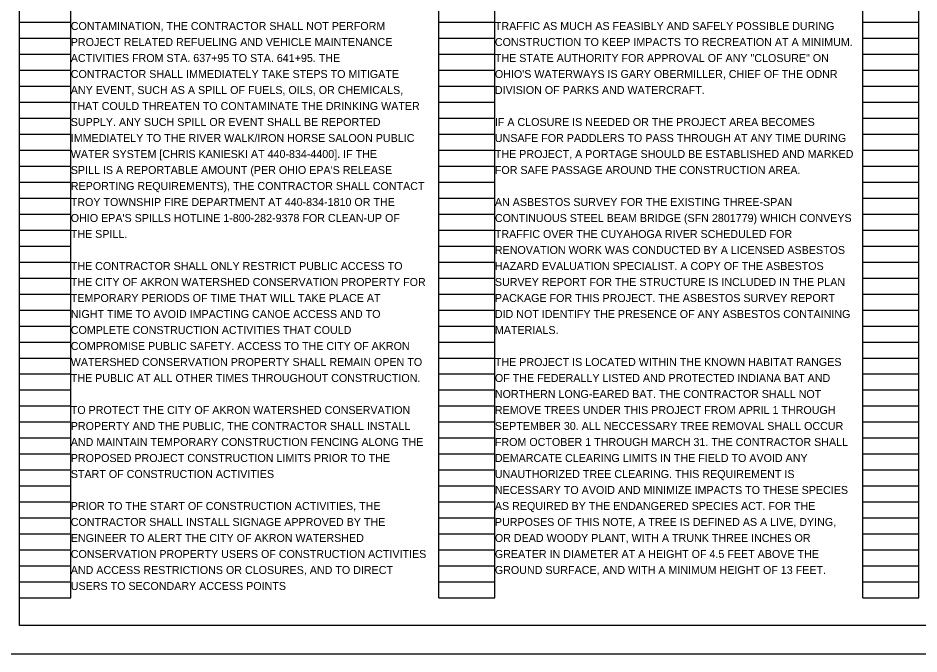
# Model space of a CAD drawing. Extents: x -6.4 to 41.8, y 0 to 22.
# Drawn here: x 1.98 to 17.74, y 0 to 11.13 of the extents above; entities that cross this region are included whole.
import ezdxf

# ---------------------------------------------------------------- set-up
doc = ezdxf.new("R2010")
doc.units = 0
for name, color, linetype in [('SC_Scratch1', 7, 'Continuous'), ('SH_Border', 7, 'Continuous'), ('SH_Cut_Line', 7, 'Continuous'), ('SH_Text', 7, 'Continuous')]:
    doc.layers.add(name, color=color, linetype=linetype)

msp = doc.modelspace()

# ---------------------------------------------------------------- linework, layer by layer
at = {"layer": 'SC_Scratch1'}
for p, q in [((2, 0.98), (2, 21.14)), ((2.9, 0.98), (2.9, 21.14)), ((9.34, 0.98), (9.34, 21.14)), ((10.32, 0.98), (10.32, 21.14)), ((16.76, 0.98), (16.76, 21.14)), ((17.74, 0.98), (17.74, 21.14)), ((2, 11.06), (2.9, 11.06)), ((9.34, 11.06), (10.32, 11.06)), ((16.76, 11.06), (17.74, 11.06)), ((2, 10.78), (2.9, 10.78)), ((9.34, 10.78), (10.32, 10.78)), ((16.76, 10.78), (17.74, 10.78)), ((2, 10.5), (2.9, 10.5)), ((9.34, 10.5), (10.32, 10.5)), ((16.76, 10.5), (17.74, 10.5)), ((2, 10.22), (2.9, 10.22)), ((9.34, 10.22), (10.32, 10.22)), ((16.76, 10.22), (17.74, 10.22)), ((2, 9.94), (2.9, 9.94)), ((9.34, 9.94), (10.32, 9.94)), ((16.76, 9.94), (17.74, 9.94)), ((2, 9.66), (2.9, 9.66)), ((9.34, 9.66), (10.32, 9.66)), ((16.76, 9.66), (17.74, 9.66)), ((2, 9.38), (2.9, 9.38)), ((9.34, 9.38), (10.32, 9.38)), ((16.76, 9.38), (17.74, 9.38)), ((2, 9.1), (2.9, 9.1)), ((9.34, 9.1), (10.32, 9.1)), ((16.76, 9.1), (17.74, 9.1)), ((2, 8.82), (2.9, 8.82)), ((9.34, 8.82), (10.32, 8.82)), ((16.76, 8.82), (17.74, 8.82)), ((2, 8.54), (2.9, 8.54)), ((9.34, 8.54), (10.32, 8.54)), ((16.76, 8.54), (17.74, 8.54)), ((2, 8.26), (2.9, 8.26)), ((9.34, 8.26), (10.32, 8.26)), ((16.76, 8.26), (17.74, 8.26)), ((2, 7.98), (2.9, 7.98)), ((9.34, 7.98), (10.32, 7.98)), ((16.76, 7.98), (17.74, 7.98)), ((2, 7.7), (2.9, 7.7)), ((9.34, 7.7), (10.32, 7.7)), ((16.76, 7.7), (17.74, 7.7)), ((2, 7.42), (2.9, 7.42)), ((9.34, 7.42), (10.32, 7.42)), ((16.76, 7.42), (17.74, 7.42)), ((2, 7.14), (2.9, 7.14)), ((9.34, 7.14), (10.32, 7.14)), ((16.76, 7.14), (17.74, 7.14)), ((2, 6.86), (2.9, 6.86)), ((9.34, 6.86), (10.32, 6.86)), ((16.76, 6.86), (17.74, 6.86)), ((2, 6.58), (2.9, 6.58)), ((9.34, 6.58), (10.32, 6.58)), ((16.76, 6.58), (17.74, 6.58)), ((2, 6.3), (2.9, 6.3)), ((9.34, 6.3), (10.32, 6.3)), ((16.76, 6.3), (17.74, 6.3)), ((2, 6.02), (2.9, 6.02)), ((9.34, 6.02), (10.32, 6.02)), ((16.76, 6.02), (17.74, 6.02)), ((2, 5.74), (2.9, 5.74)), ((9.34, 5.74), (10.32, 5.74)), ((16.76, 5.74), (17.74, 5.74)), ((2, 5.46), (2.9, 5.46)), ((9.34, 5.46), (10.32, 5.46)), ((16.76, 5.46), (17.74, 5.46)), ((2, 5.18), (2.9, 5.18)), ((9.34, 5.18), (10.32, 5.18)), ((16.76, 5.18), (17.74, 5.18)), ((2, 4.9), (2.9, 4.9)), ((9.34, 4.9), (10.32, 4.9)), ((16.76, 4.9), (17.74, 4.9)), ((2, 4.62), (2.9, 4.62)), ((9.34, 4.62), (10.32, 4.62)), ((16.76, 4.62), (17.74, 4.62)), ((2, 4.34), (2.9, 4.34)), ((9.34, 4.34), (10.32, 4.34)), ((16.76, 4.34), (17.74, 4.34)), ((2, 4.06), (2.9, 4.06)), ((9.34, 4.06), (10.32, 4.06)), ((16.76, 4.06), (17.74, 4.06)), ((2, 3.78), (2.9, 3.78)), ((9.34, 3.78), (10.32, 3.78)), ((16.76, 3.78), (17.74, 3.78)), ((2, 3.5), (2.9, 3.5)), ((9.34, 3.5), (10.32, 3.5)), ((16.76, 3.5), (17.74, 3.5)), ((2, 3.22), (2.9, 3.22)), ((9.34, 3.22), (10.32, 3.22)), ((16.76, 3.22), (17.74, 3.22)), ((2, 2.94), (2.9, 2.94)), ((9.34, 2.94), (10.32, 2.94)), ((16.76, 2.94), (17.74, 2.94)), ((2, 2.66), (2.9, 2.66)), ((9.34, 2.66), (10.32, 2.66)), ((16.76, 2.66), (17.74, 2.66)), ((2, 2.38), (2.9, 2.38)), ((9.34, 2.38), (10.32, 2.38)), ((16.76, 2.38), (17.74, 2.38)), ((2, 2.1), (2.9, 2.1)), ((9.34, 2.1), (10.32, 2.1)), ((16.76, 2.1), (17.74, 2.1)), ((2, 1.82), (2.9, 1.82)), ((9.34, 1.82), (10.32, 1.82)), ((16.76, 1.82), (17.74, 1.82)), ((2, 1.54), (2.9, 1.54)), ((9.34, 1.54), (10.32, 1.54)), ((16.76, 1.54), (17.74, 1.54)), ((2, 1.26), (2.9, 1.26)), ((9.34, 1.26), (10.32, 1.26)), ((16.76, 1.26), (17.74, 1.26)), ((2, 0.98), (2.9, 0.98)), ((9.34, 0.98), (10.32, 0.98)), ((16.76, 0.98), (17.74, 0.98))]:
    msp.add_line(p, q, dxfattribs=at)
at = {"layer": 'SH_Border'}
msp.add_lwpolyline([(2, 21.5), (33.5, 21.5), (33.5, 0.5), (2, 0.5)], close=True, dxfattribs=at)
at = {"layer": 'SH_Cut_Line'}
msp.add_lwpolyline([(0, 0), (34, 0), (34, 22), (0, 22)], close=True, dxfattribs=at)

# ---------------------------------------------------------------- texts
at = {"layer": 'SH_Text'}
for s, p in [('CONTAMINATION, THE CONTRACTOR SHALL NOT PERFORM ', (2.9, 10.92)), ('TRAFFIC AS MUCH AS FEASIBLY AND SAFELY POSSIBLE DURING ', (10.32, 10.92)), ('PROJECT RELATED REFUELING AND VEHICLE MAINTENANCE ', (2.9, 10.64)), ('CONSTRUCTION TO KEEP IMPACTS TO RECREATION AT A MINIMUM. ', (10.32, 10.64)), ('ACTIVITIES FROM STA. 637+95 TO STA. 641+95. THE ', (2.9, 10.36)), ('THE STATE AUTHORITY FOR APPROVAL OF ANY "CLOSURE" ON ', (10.32, 10.36)), ('CONTRACTOR SHALL IMMEDIATELY TAKE STEPS TO MITIGATE ', (2.9, 10.08)), ("OHIO'S WATERWAYS IS GARY OBERMILLER, CHIEF OF THE ODNR ", (10.32, 10.08)), ('ANY EVENT, SUCH AS A SPILL OF FUELS, OILS, OR CHEMICALS, ', (2.9, 9.8)), ('DIVISION OF PARKS AND WATERCRAFT. ', (10.32, 9.8)), ('THAT COULD THREATEN TO CONTAMINATE THE DRINKING WATER ', (2.9, 9.52)), ('SUPPLY. ANY SUCH SPILL OR EVENT SHALL BE REPORTED ', (2.9, 9.24)), ('IF A CLOSURE IS NEEDED OR THE PROJECT AREA BECOMES ', (10.32, 9.24)), ('IMMEDIATELY TO THE RIVER WALK/IRON HORSE SALOON PUBLIC ', (2.9, 8.96)), ('UNSAFE FOR PADDLERS TO PASS THROUGH AT ANY TIME DURING ', (10.32, 8.96)), ('WATER SYSTEM [CHRIS KANIESKI AT 440-834-4400]. IF THE ', (2.9, 8.68)), ('THE PROJECT, A PORTAGE SHOULD BE ESTABLISHED AND MARKED ', (10.32, 8.68)), ("SPILL IS A REPORTABLE AMOUNT (PER OHIO EPA'S RELEASE ", (2.9, 8.4)), ('FOR SAFE PASSAGE AROUND THE CONSTRUCTION AREA. ', (10.32, 8.4)), ('REPORTING REQUIREMENTS), THE CONTRACTOR SHALL CONTACT ', (2.9, 8.12)), ('TROY TOWNSHIP FIRE DEPARTMENT AT 440-834-1810 OR THE ', (2.9, 7.84)), ('AN ASBESTOS SURVEY FOR THE EXISTING THREE-SPAN ', (10.32, 7.84)), ("OHIO EPA'S SPILLS HOTLINE 1-800-282-9378 FOR CLEAN-UP OF ", (2.9, 7.56)), ('CONTINUOUS STEEL BEAM BRIDGE (SFN 2801779) WHICH CONVEYS ', (10.32, 7.56)), ('THE SPILL. ', (2.9, 7.28)), ('TRAFFIC OVER THE CUYAHOGA RIVER SCHEDULED FOR ', (10.32, 7.28)), ('RENOVATION WORK WAS CONDUCTED BY A LICENSED ASBESTOS ', (10.32, 7)), ('THE CONTRACTOR SHALL ONLY RESTRICT PUBLIC ACCESS TO ', (2.9, 6.72)), ('HAZARD EVALUATION SPECIALIST. A COPY OF THE ASBESTOS ', (10.32, 6.72)), ('THE CITY OF AKRON WATERSHED CONSERVATION PROPERTY FOR ', (2.9, 6.44)), ('SURVEY REPORT FOR THE STRUCTURE IS INCLUDED IN THE PLAN ', (10.32, 6.44)), ('TEMPORARY PERIODS OF TIME THAT WILL TAKE PLACE AT ', (2.9, 6.16)), ('PACKAGE FOR THIS PROJECT. THE ASBESTOS SURVEY REPORT ', (10.32, 6.16)), ('NIGHT TIME TO AVOID IMPACTING CANOE ACCESS AND TO ', (2.9, 5.88)), ('DID NOT IDENTIFY THE PRESENCE OF ANY ASBESTOS CONTAINING ', (10.32, 5.88)), ('COMPLETE CONSTRUCTION ACTIVITIES THAT COULD ', (2.9, 5.6)), ('MATERIALS. ', (10.32, 5.6)), ('COMPROMISE PUBLIC SAFETY. ACCESS TO THE CITY OF AKRON ', (2.9, 5.32)), ('WATERSHED CONSERVATION PROPERTY SHALL REMAIN OPEN TO ', (2.9, 5.04)), ('THE PROJECT IS LOCATED WITHIN THE KNOWN HABITAT RANGES ', (10.32, 5.04)), ('THE PUBLIC AT ALL OTHER TIMES THROUGHOUT CONSTRUCTION. ', (2.9, 4.76)), ('OF THE FEDERALLY LISTED AND PROTECTED INDIANA BAT AND ', (10.32, 4.76)), ('NORTHERN LONG-EARED BAT. THE CONTRACTOR SHALL NOT ', (10.32, 4.48)), ('TO PROTECT THE CITY OF AKRON WATERSHED CONSERVATION ', (2.9, 4.2)), ('REMOVE TREES UNDER THIS PROJECT FROM APRIL 1 THROUGH ', (10.32, 4.2)), ('PROPERTY AND THE PUBLIC, THE CONTRACTOR SHALL INSTALL ', (2.9, 3.92)), ('SEPTEMBER 30. ALL NECCESSARY TREE REMOVAL SHALL OCCUR ', (10.32, 3.92)), ('AND MAINTAIN TEMPORARY CONSTRUCTION FENCING ALONG THE ', (2.9, 3.64)), ('FROM OCTOBER 1 THROUGH MARCH 31. THE CONTRACTOR SHALL ', (10.32, 3.64)), ('PROPOSED PROJECT CONSTRUCTION LIMITS PRIOR TO THE ', (2.9, 3.36)), ('DEMARCATE CLEARING LIMITS IN THE FIELD TO AVOID ANY ', (10.32, 3.36)), ('START OF CONSTRUCTION ACTIVITIES', (2.9, 3.08)), ('UNAUTHORIZED TREE CLEARING. THIS REQUIREMENT IS ', (10.32, 3.08)), ('NECESSARY TO AVOID AND MINIMIZE IMPACTS TO THESE SPECIES ', (10.32, 2.8)), ('PRIOR TO THE START OF CONSTRUCTION ACTIVITIES, THE ', (2.9, 2.52)), ('AS REQUIRED BY THE ENDANGERED SPECIES ACT. FOR THE ', (10.32, 2.52)), ('CONTRACTOR SHALL INSTALL SIGNAGE APPROVED BY THE ', (2.9, 2.24)), ('PURPOSES OF THIS NOTE, A TREE IS DEFINED AS A LIVE, DYING, ', (10.32, 2.24)), ('ENGINEER TO ALERT THE CITY OF AKRON WATERSHED ', (2.9, 1.96)), ('OR DEAD WOODY PLANT, WITH A TRUNK THREE INCHES OR ', (10.32, 1.96)), ('CONSERVATION PROPERTY USERS OF CONSTRUCTION ACTIVITIES ', (2.9, 1.68)), ('GREATER IN DIAMETER AT A HEIGHT OF 4.5 FEET ABOVE THE ', (10.32, 1.68)), ('AND ACCESS RESTRICTIONS OR CLOSURES, AND TO DIRECT ', (2.9, 1.4)), ('GROUND SURFACE, AND WITH A MINIMUM HEIGHT OF 13 FEET. ', (10.32, 1.4)), ('USERS TO SECONDARY ACCESS POINTS', (2.9, 1.12))]:
    msp.add_text(s, height=0.14, dxfattribs=at).set_placement(p)

doc.saveas('drawing.dxf')
